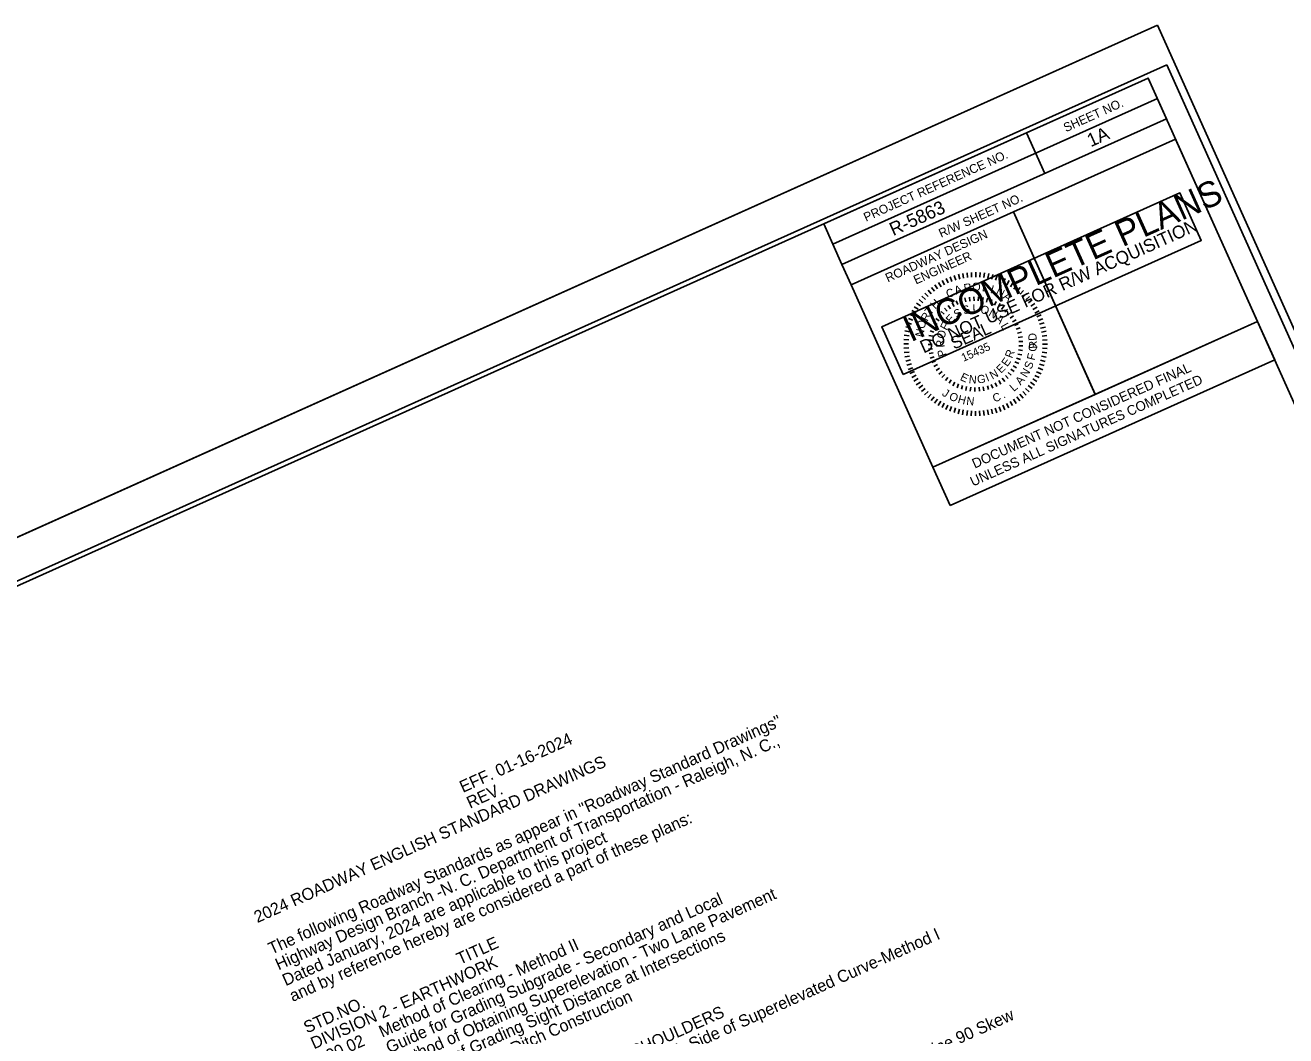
# Model space of a CAD drawing. Extents: x 553377 to 556641, y 502653 to 504402.
# Drawn here: x 554838 to 555547, y 503778 to 504347 of the extents above; entities that cross this region are included whole.
import ezdxf

# ---------------------------------------------------------------- set-up
doc = ezdxf.new("R2010")
doc.units = 0
for name, color, linetype in [('Old_Level_21', 7, 'Continuous'), ('Prop Dimension Text', 7, 'Continuous'), ('Sheet Border Standard 30in CELL', 7, 'Continuous'), ('Sheet Cutting Line CELL', 7, 'Continuous'), ('Sheet Data Field CELL', 7, 'Continuous'), ('Sheet Plot Border Inside CELL', 7, 'Continuous'), ('Sheet Plot Border Outside CELL', 7, 'Continuous'), ('Sheet Sticker Exception Certification CELL', 7, 'Continuous'), ('Sheet Sticker Incomplete CELL', 7, 'Continuous')]:
    doc.layers.add(name, color=color, linetype=linetype)

msp = doc.modelspace()

# ---------------------------------------------------------------- linework, layer by layer
at = {"layer": 'Old_Level_21'}
for p, q in [((555356, 504204.17), (555357.12, 504201.66)), ((555358.26, 504205.1), (555359.23, 504202.53)), ((555360.57, 504205.89), (555361.38, 504203.27)), ((555362.92, 504206.55), (555363.57, 504203.87)), ((555365.3, 504207.05), (555365.8, 504204.34)), ((555367.72, 504207.42), (555368.05, 504204.68)), ((555370.15, 504207.63), (555370.31, 504204.88)), ((555372.59, 504207.69), (555372.59, 504204.94)), ((555375.03, 504207.62), (555374.86, 504204.87)), ((555377.46, 504207.39), (555377.12, 504204.66)), ((555379.88, 504207.02), (555379.37, 504204.31)), ((555382.26, 504206.5), (555381.6, 504203.83)), ((555384.61, 504205.84), (555383.79, 504203.21)), ((555386.92, 504205.04), (555385.93, 504202.47)), ((555389.17, 504204.1), (555388.03, 504201.59)), ((555345.77, 504197.6), (555347.59, 504195.53)), ((555347.65, 504199.16), (555349.34, 504196.98)), ((555349.62, 504200.6), (555351.18, 504198.33)), ((555351.67, 504201.92), (555353.09, 504199.56)), ((555353.8, 504203.11), (555355.07, 504200.67)), ((555391.36, 504203.03), (555390.08, 504200.59)), ((555393.49, 504201.82), (555392.06, 504199.47)), ((555395.53, 504200.49), (555393.97, 504198.23)), ((555397.5, 504199.04), (555395.79, 504196.88)), ((555399.37, 504197.47), (555397.54, 504195.42)), ((555339.29, 504190.32), (555341.56, 504188.75)), ((555340.74, 504192.28), (555342.91, 504190.58)), ((555342.32, 504194.15), (555344.37, 504192.32)), ((555343.99, 504195.93), (555345.94, 504193.97)), ((555359.33, 504190.43), (555360.46, 504188.44)), ((555361.63, 504191.6), (555362.56, 504189.5)), ((555362.56, 504189.5), (555361.63, 504191.6)), ((555364.02, 504192.53), (555364.75, 504190.36)), ((555366.5, 504193.23), (555367.02, 504191)), ((555369.03, 504193.69), (555369.33, 504191.42)), ((555371.6, 504193.91), (555371.68, 504191.61)), ((555374.17, 504193.87), (555374.03, 504191.58)), ((555376.73, 504193.58), (555376.36, 504191.32)), ((555379.25, 504193.05), (555378.67, 504190.83)), ((555381.7, 504192.28), (555380.91, 504190.12)), ((555384.07, 504191.28), (555383.07, 504189.21)), ((555386.33, 504190.05), (555385.14, 504188.08)), ((555401.14, 504195.8), (555399.19, 504193.85)), ((555402.81, 504194.02), (555400.74, 504192.19)), ((555404.37, 504192.14), (555402.2, 504190.45)), ((555405.81, 504190.17), (555403.54, 504188.61)), ((555335.69, 504183.95), (555338.2, 504182.82)), ((555336.76, 504186.15), (555339.19, 504184.86)), ((555337.96, 504188.27), (555340.32, 504186.84)), ((555351.57, 504183.76), (555353.37, 504182.34)), ((555353.26, 504185.7), (555354.92, 504184.11)), ((555355.13, 504187.48), (555356.62, 504185.73)), ((555357.16, 504189.06), (555358.48, 504187.18)), ((555388.46, 504188.61), (555387.09, 504186.77)), ((555390.45, 504186.97), (555388.9, 504185.27)), ((555392.26, 504185.14), (555390.56, 504183.6)), ((555393.89, 504183.15), (555392.05, 504181.79)), ((555407.13, 504188.11), (555404.77, 504186.7)), ((555408.33, 504185.99), (555405.88, 504184.71)), ((555409.39, 504183.79), (555406.88, 504182.66)), ((555333.28, 504177.04), (555335.96, 504176.38)), ((555333.95, 504179.4), (555336.57, 504178.57)), ((555334.75, 504181.7), (555337.32, 504180.72)), ((555347.74, 504177.09), (555349.87, 504176.24)), ((555348.79, 504179.43), (555350.84, 504178.38)), ((555350.08, 504181.66), (555352.01, 504180.42)), ((555395.33, 504181.01), (555393.36, 504179.83)), ((555396.55, 504178.75), (555394.48, 504177.76)), ((555397.54, 504176.37), (555395.38, 504175.59)), ((555410.32, 504181.53), (555407.74, 504180.56)), ((555411.11, 504179.22), (555408.48, 504178.41)), ((555411.76, 504176.87), (555409.09, 504176.21)), ((555332.17, 504169.82), (555334.92, 504169.64)), ((555332.39, 504172.25), (555335.13, 504171.91)), ((555332.77, 504174.66), (555335.47, 504174.16)), ((555345.97, 504169.6), (555348.25, 504169.39)), ((555346.31, 504172.15), (555348.57, 504171.72)), ((555346.91, 504174.65), (555349.11, 504174.02)), ((555396.05, 504173.42), (555398.28, 504174)), ((555398.82, 504171.39), (555396.55, 504171.04)), ((555399.09, 504168.83), (555396.8, 504168.7)), ((555412.27, 504174.48), (555409.56, 504173.99)), ((555412.63, 504172.06), (555409.89, 504171.74)), ((555412.85, 504169.64), (555410.09, 504169.48)), ((555332.09, 504167.38), (555334.84, 504167.37)), ((555332.15, 504164.93), (555334.91, 504165.09)), ((555332.37, 504162.51), (555335.11, 504162.83)), ((555345.87, 504167.02), (555348.16, 504167.05)), ((555346.02, 504164.45), (555348.3, 504164.7)), ((555346.41, 504161.91), (555348.66, 504162.38)), ((555398.43, 504161.16), (555396.19, 504161.69)), ((555398.89, 504163.7), (555396.62, 504164)), ((555399.11, 504166.26), (555396.82, 504166.35)), ((555412.61, 504162.32), (555409.88, 504162.66)), ((555412.84, 504164.76), (555410.08, 504164.93)), ((555412.91, 504167.2), (555410.16, 504167.2)), ((555332.73, 504160.09), (555335.44, 504160.58)), ((555333.24, 504157.7), (555335.91, 504158.36)), ((555333.89, 504155.35), (555336.52, 504156.16)), ((555347.05, 504159.42), (555349.24, 504160.1)), ((555347.93, 504157), (555350.05, 504157.88)), ((555349.04, 504154.68), (555351.06, 504155.76)), ((555395.59, 504154.01), (555393.6, 504155.15)), ((555396.77, 504156.3), (555394.67, 504157.25)), ((555397.71, 504158.69), (555395.54, 504159.43)), ((555411.06, 504155.17), (555408.43, 504156)), ((555411.72, 504157.53), (555409.05, 504158.19)), ((555412.24, 504159.91), (555409.53, 504160.41)), ((555334.68, 504153.04), (555337.26, 504154.01)), ((555335.61, 504150.78), (555338.13, 504151.91)), ((555336.68, 504148.58), (555339.12, 504149.86)), ((555337.87, 504146.46), (555340.23, 504147.87)), ((555350.37, 504152.47), (555352.27, 504153.75)), ((555351.9, 504150.4), (555353.67, 504151.86)), ((555353.63, 504148.49), (555355.25, 504150.11)), ((555355.53, 504146.76), (555356.99, 504148.53)), ((555388.88, 504146.28), (555387.47, 504148.09)), ((555390.83, 504147.96), (555389.25, 504149.63)), ((555392.61, 504149.82), (555390.88, 504151.33)), ((555394.2, 504151.84), (555392.33, 504153.17)), ((555407.04, 504146.3), (555404.69, 504147.73)), ((555408.24, 504148.42), (555405.81, 504149.71)), ((555409.32, 504150.62), (555406.81, 504151.75)), ((555410.25, 504152.87), (555407.68, 504153.85)), ((555339.19, 504144.4), (555341.46, 504145.96)), ((555340.63, 504142.44), (555342.8, 504144.12)), ((555342.19, 504140.55), (555344.26, 504142.38)), ((555343.86, 504138.77), (555345.81, 504140.72)), ((555357.58, 504145.22), (555358.87, 504147.12)), ((555359.79, 504143.88), (555360.88, 504145.9)), ((555362.1, 504142.76), (555363, 504144.87)), ((555364.52, 504141.87), (555365.21, 504144.07)), ((555367.01, 504141.22), (555367.48, 504143.47)), ((555369.55, 504140.81), (555369.8, 504143.1)), ((555372.12, 504140.66), (555372.15, 504142.95)), ((555374.69, 504140.74), (555374.5, 504143.03)), ((555376.82, 504143.33), (555377.23, 504141.07)), ((555379.75, 504141.66), (555379.13, 504143.86)), ((555382.19, 504142.47), (555381.35, 504144.61)), ((555384.54, 504143.52), (555383.5, 504145.57)), ((555386.78, 504144.8), (555385.55, 504146.74)), ((555401.01, 504138.64), (555399.07, 504140.6)), ((555402.69, 504140.42), (555400.63, 504142.25)), ((555404.26, 504142.29), (555402.09, 504143.99)), ((555405.71, 504144.25), (555403.44, 504145.82)), ((555345.64, 504137.1), (555347.47, 504139.15)), ((555347.5, 504135.53), (555349.21, 504137.69)), ((555349.47, 504134.08), (555351.04, 504136.34)), ((555351.52, 504132.75), (555352.95, 504135.1)), ((555353.64, 504131.55), (555354.93, 504133.98)), ((555391.2, 504131.46), (555389.93, 504133.9)), ((555393.33, 504132.66), (555391.91, 504135.01)), ((555395.38, 504133.97), (555393.83, 504136.24)), ((555397.35, 504135.41), (555395.66, 504137.59)), ((555399.23, 504136.97), (555397.41, 504139.04)), ((555355.83, 504130.47), (555356.97, 504132.98)), ((555358.09, 504129.53), (555359.07, 504132.1)), ((555360.39, 504128.73), (555361.22, 504131.36)), ((555362.74, 504128.07), (555363.41, 504130.74)), ((555365.13, 504127.55), (555365.63, 504130.26)), ((555367.54, 504127.18), (555367.88, 504129.91)), ((555369.97, 504126.95), (555370.14, 504129.7)), ((555372.41, 504126.88), (555372.41, 504129.63)), ((555374.85, 504126.94), (555374.69, 504129.69)), ((555377.28, 504127.15), (555376.95, 504129.89)), ((555379.7, 504127.52), (555379.2, 504130.23)), ((555382.08, 504128.02), (555381.43, 504130.7)), ((555384.44, 504128.68), (555383.62, 504131.31)), ((555386.75, 504129.47), (555385.77, 504132.04)), ((555389, 504130.4), (555387.88, 504132.91))]:
    msp.add_line(p, q, dxfattribs=at)
at = {"layer": 'Sheet Border Standard 30in CELL'}
for p, q in [((555292.25, 504223.45), (555474.75, 504305.4)), ((555297.37, 504212.05), (555479.87, 504294)), ((555297.37, 504212.05), (555479.87, 504294)), ((555401.21, 504286.08), (555411.45, 504263.27)), ((555393.76, 504241.63), (555439.82, 504139.05)), ((555297.37, 504212.05), (555302.49, 504200.65))]:
    msp.add_line(p, q, dxfattribs=at)
for points in [[(555469.6, 504316.85), (554101.23, 503702.4), (554531.34, 502744.54), (555899.72, 503358.98)], [(555287.11, 504234.9), (555469.6, 504316.85), (555479.87, 504294), (555297.37, 504212.05)], [(555393.76, 504241.63), (555484.99, 504282.59), (555531.07, 504179.96), (555439.84, 504139)], [(555302.49, 504200.65), (555393.76, 504241.63), (555439.84, 504139), (555348.57, 504098.02)]]:
    msp.add_lwpolyline(points, close=True, dxfattribs=at)
at = {"layer": 'Sheet Cutting Line CELL'}
msp.add_line((555474.87, 504346.62), (553938.64, 503656.8), dxfattribs=at)
at = {"layer": 'Sheet Plot Border Inside CELL'}
msp.add_lwpolyline([(555479.96, 504324.29), (553959.7, 503641.65), (554391.9, 502679.13), (555912.16, 503361.78)], close=True, dxfattribs=at)
at = {"layer": 'Sheet Plot Border Outside CELL'}
msp.add_lwpolyline([(555474.87, 504346.62), (553938.64, 503656.8), (554389.23, 502653.32), (555925.47, 503343.14)], close=True, dxfattribs=at)
at = {"layer": 'Sheet Sticker Exception Certification CELL'}
for p, q in [((555348.57, 504098.02), (555531.06, 504179.96)), ((555531.06, 504179.95), (555540.69, 504158.51)), ((555540.68, 504158.52), (555358.2, 504076.58)), ((555358.2, 504076.58), (555348.57, 504098.02))]:
    msp.add_line(p, q, dxfattribs=at)
at = {"layer": 'Sheet Sticker Incomplete CELL'}
msp.add_lwpolyline([(555331.81, 504150.28), (555319.77, 504177.08), (555487.4, 504252.35), (555499.43, 504225.55)], close=True, dxfattribs=at)

# ---------------------------------------------------------------- texts
at = {"layer": 'Old_Level_21'}
for s, height, rotation, p in [('C', 4.59, 21.4587, (555356.94, 504193.08)), ('A', 4.59, 21.4587, (555361.56, 504195.04)), ('R', 4.59, 9.4494, (555366.27, 504196.41)), ('O', 4.59, 6.39258, (555370.87, 504197.02)), ('L', 4.59, 353.2563, (555375.96, 504197.06)), ('I', 4.59, 343.68083, (555380.42, 504196.14)), ('N', 4.59, 334.38637, (555383.41, 504195.1)), ('H', 4.59, 45.1694, (555349.81, 504186.66)), ('A', 4.59, 324.61884, (555387.55, 504193.25)), ('R', 4.59, 62.7623, (555345.49, 504179.72)), ('T', 4.59, 54.60134, (555347.26, 504183.32)), ('E', 4.59, 47.04611, (555358.63, 504178.46)), ('S', 4.59, 31.74986, (555361.92, 504181.66)), ('S', 4.59, 16.45362, (555365.95, 504183.88)), ('I', 4.59, 1.15737, (555370.81, 504184.97)), ('O', 4.59, 345.86113, (555374.91, 504184.85)), ('N', 4.59, 330.56488, (555379.39, 504183.49)), ('A', 4.59, 315.26863, (555383.22, 504181.08)), ('N', 4.59, 77.77847, (555342.9, 504170.93)), ('O', 4.59, 75.81904, (555343.72, 504175.54)), ('F', 4.59, 62.34235, (555356.34, 504174.6)), ('SEAL', 6.886, 24.10174, (555360.4, 504164.13)), ('L', 4.59, 299.97239, (555386.43, 504177.55)), ('R', 4.59, 92.93485, (555355.1, 504165.47)), ('O', 4.59, 77.6386, (555355.07, 504169.97)), (' RD', 4.587, 93.77416, (555407.33, 504163.16)), ('P', 4.59, 108.23109, (555356.32, 504161.04)), ('15435', 4.587, 24.10174, (555365.72, 504157.27)), ('R', 4.59, 68.66663, (555393.06, 504158.97)), ('F', 4.59, 76.3088, (555405.69, 504157.86)), ('O ', 4.587, 85.10141, (555406.73, 504162.87)), ('E', 4.59, 44.90966, (555386.88, 504150.55)), ('E', 4.59, 54.89554, (555390.37, 504154.26)), ('S', 4.59, 67.42617, (555403.8, 504152.75)), ('E', 4.59, 334.17183, (555363.44, 504147.27)), ('N', 4.59, 355.0269, (555368.52, 504145.35)), ('G', 4.59, 3.79314, (555373.5, 504145.22)), ('I', 4.59, 21.88793, (555379.09, 504146.12)), ('N', 4.59, 29.5176, (555381.99, 504147.25)), ('A', 4.59, 49.72092, (555397.85, 504143.86)), ('N', 4.59, 58.54354, (555401.18, 504148.09)), ('J', 4.59, 328.03675, (555353.29, 504138.63)), ('L', 4.59, 40.71836, (555394.01, 504140.3)), ('O', 4.59, 336.10857, (555357.18, 504136.36)), ('H', 4.59, 344.75132, (555362.17, 504134.36)), ('N', 4.59, 353.4239, (555367.15, 504133.19)), ('C', 4.59, 20.19169, (555383.08, 504134.44)), ('.', 4.59, 27.93404, (555388.33, 504136.65))]:
    msp.add_text(s, height=height, rotation=rotation, dxfattribs=at).set_placement(p)
at = {"layer": 'Prop Dimension Text'}
for s, p in [('The following Roadway Standards as appear in "Roadway Standard Drawings" ', (554976.65, 503823.89)), ('Highway Design Branch -N. C. Department of Transportation - Raleigh, N. C., ', (554980.63, 503815.02)), ('                                                      EFF. 01-16-2024', (554960.71, 503859.38)), ('2024 ROADWAY ENGLISH STANDARD DRAWINGS', (554968.68, 503841.64)), ('                                                      REV. ', (554964.7, 503850.51)), ('and by reference hereby are considered a part of these plans:', (554988.6, 503797.27)), ('Dated January, 2024 are applicable to this project', (554984.62, 503806.15)), ('225.02    Guide for Grading Subgrade - Secondary and Local', (555008.52, 503752.91)), ('225.04    Method of Obtaining Superelevation - Two Lane Pavement', (555012.51, 503744.04)), ('225.06    Method of Grading Sight Distance at Intersections', (555016.49, 503735.16)), ('560.01    Method of Shoulder Construction-High Side of Superelevated Curve-Method I', (555036.41, 503690.8)), ('STD.NO.                       TITLE', (554996.57, 503779.53)), ('200.02    Method of Clearing - Method II', (555004.54, 503761.78)), ('DIVISION 2 - EARTHWORK', (555000.55, 503770.65)), ('240.01    Guide for Berm Ditch Construction', (555020.47, 503726.29)), ('DIVISION 5- SUBGRADE, BASES AND SHOULDERS', (555032.43, 503699.67)), ('838.01    Concrete Endwall for Single and Double Pipe Culverts - 15" thru 48" Pipe 90 Skew', (555060.32, 503637.56))]:
    msp.add_text(s, height=6.75, rotation=24.18158, dxfattribs=at).set_placement(p)
at = {"layer": 'Sheet Border Standard 30in CELL'}
for s, height, p in [('SHEET NO.', 5, (555423.31, 504286.41)), ('PROJECT REFERENCE NO.', 5.0001, (555310.92, 504236.06)), ('R/W SHEET NO.', 5.0001, (555353.14, 504227.01)), ('ROADWAY DESIGN', 5.0001, (555323.18, 504201.93)), ('ENGINEER', 5, (555339, 504200.76))]:
    msp.add_text(s, height=height, rotation=24.18158, dxfattribs=at).set_placement(p)
at = {"layer": 'Sheet Data Field CELL'}
for s, p in [('1A ', (555437.29, 504277.95)), ('R-5863   ', (555326.18, 504228))]:
    msp.add_text(s, height=7.5, rotation=24.18158, dxfattribs=at).set_placement(p)
at = {"layer": 'Sheet Sticker Exception Certification CELL'}
for s, p in [('DOCUMENT NOT CONSIDERED FINAL', (555372.03, 504097.21)), ('UNLESS ALL SIGNATURES COMPLETED', (555371.01, 504087.11))]:
    msp.add_text(s, height=5.5, rotation=24.18158, dxfattribs=at).set_placement(p)
at = {"layer": 'Sheet Sticker Incomplete CELL'}
for s, height, p in [('INCOMPLETE PLANS', 14.4, (555336.03, 504168.23)), ('DO NOT USE FOR R/W ACQUISITION', 7.2, (555343.29, 504161.97))]:
    msp.add_text(s, height=height, rotation=24.18158, dxfattribs=at).set_placement(p)

doc.saveas('drawing.dxf')
